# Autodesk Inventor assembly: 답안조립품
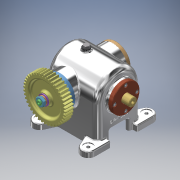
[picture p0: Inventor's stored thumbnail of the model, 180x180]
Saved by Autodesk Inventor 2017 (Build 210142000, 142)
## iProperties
Part Number: 답안조립품
Material: 일반
Document SubType Name: Assembly
Designer: MRC
Author: MRC
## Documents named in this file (17)
- C:\Users\MRC\Desktop\740904V1001\답안조립품.iam
- C:\Users\MRC\Desktop\740904V1001\본체.ipt
- C:\Users\MRC\Downloads\740904V1001\740904V1001\깊은 홈 볼베어링 6203.ipt
- C:\Users\MRC\Downloads\740904V1001\740904V1001\편심축.ipt
- C:\Users\MRC\Downloads\740904V1001\740904V1001\뒷커버.ipt
- C:\Users\MRC\Downloads\740904V1001\740904V1001\앞커버.ipt
- C:\Users\MRC\Downloads\740904V1001\740904V1001\오일실 17 32 8.ipt
- C:\Users\MRC\Downloads\740904V1001\740904V1001\육각 소켓 머리 볼트 M4x10.ipt
- C:\Users\MRC\Downloads\740904V1001\740904V1001\평행키 3x3x14.ipt
- C:\Users\MRC\Downloads\740904V1001\740904V1001\스퍼 기어.ipt
- C:\Users\MRC\Downloads\740904V1001\740904V1001\평와셔 M10.ipt
- C:\Users\MRC\Downloads\740904V1001\740904V1001\스프링와셔 M10.ipt
- C:\Users\MRC\Downloads\740904V1001\740904V1001\육각 너트 M10x1.ipt
- C:\Users\MRC\Downloads\740904V1001\740904V1001\로드.ipt
- C:\Users\MRC\Downloads\740904V1001\740904V1001\부시.ipt
- C:\Users\MRC\Downloads\740904V1001\740904V1001\실링 패드.ipt
- C:\Users\MRC\Downloads\740904V1001\740904V1001\육각 머리 볼트 M6x0.75x12.ipt
